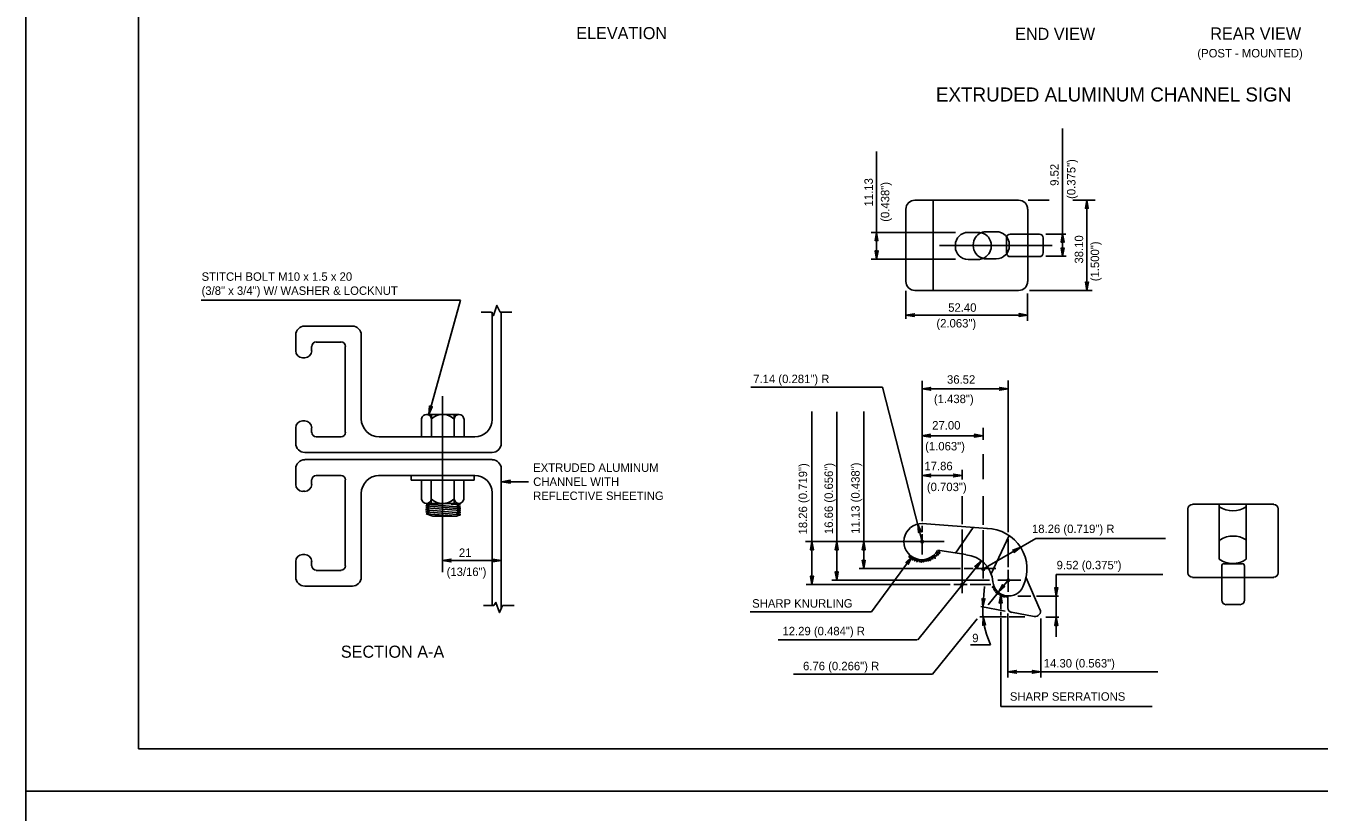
# Model space of a CAD drawing. Extents: x 647822 to 648727, y 298458 to 299646.
# Drawn here: x 647822.3 to 648281.8, y 299044.1 to 299323.4 of the extents above; entities that cross this region are included whole.
import ezdxf

# ---------------------------------------------------------------- set-up
doc = ezdxf.new("R2010")
doc.units = 0
for name, color, linetype in [('1', 7, 'Continuous'), ('2', 7, 'Continuous'), ('3', 7, 'Continuous'), ('XCS-GRID-MIN', 7, 'Continuous')]:
    doc.layers.add(name, color=color, linetype=linetype)

# ---------------------------------------------------------------- blocks, each defined once
blk = doc.blocks.new('RARROW')
at = {"layer": '3'}
blk.add_lwpolyline([(-2.2695, 0.285), (-2.184875, 0.12075), (0, 0), (-2.2695, 0.285), (-2.38575, 0.384625), (0, 0), (-2.183125, -0.108), (-2.262875, -0.2705), (0, 0), (-2.38575, -0.379125), (-2.262875, -0.2705)], dxfattribs=at)

msp = doc.modelspace()

# ---------------------------------------------------------------- linework, layer by layer
at = {"layer": '1'}
for p, q in [((647862.31, 299630.63), (647862.31, 299066.63)), ((648648.31, 299066.63), (647862.31, 299066.63)), ((647862.31, 299066.63), (648448.31, 299066.63))]:
    msp.add_line(p, q, dxfattribs=at)
at = {"layer": '2'}
for p, q in [((648190.69, 299286.92), (648190.69, 299249.57)), ((648124.58, 299278.82), (648124.58, 299250.07)), ((648134.94, 299258.32), (648134.94, 299232.7)), ((648138.19, 299261.57), (648175.06, 299261.57)), ((648144.69, 299261.57), (648144.69, 299229.45)), ((648178.31, 299258.32), (648178.31, 299232.57)), ((648178.44, 299261.57), (648185.95, 299261.57)), ((648194.36, 299261.57), (648202.19, 299261.57)), ((648199.31, 299261.57), (648199.31, 299229.45)), ((648122.7, 299250.07), (648152.6, 299250.07)), ((648124.58, 299250.07), (648124.58, 299240.57)), ((648160.69, 299250.07), (648157.06, 299250.07)), ((648163.25, 299250.31), (648167.12, 299250.31)), ((648178.31, 299249.45), (648172.06, 299249.45)), ((648178.31, 299249.45), (648182.46, 299249.45)), ((648184.69, 299249.45), (648191.81, 299249.45)), ((648190.69, 299249.57), (648190.69, 299241.57)), ((648146.94, 299245.45), (648187.02, 299245.45)), ((648152.56, 299245.57), (648152.56, 299244.95)), ((648158.94, 299245.32), (648158.94, 299245.7)), ((648165.31, 299245.07), (648165.31, 299245.45)), ((648170.71, 299248.1), (648170.71, 299242.8)), ((648171.74, 299245.69), (648171.74, 299245.31)), ((648183.81, 299248.1), (648183.81, 299242.8)), ((648122.7, 299240.57), (648152.6, 299240.57)), ((648124.58, 299240.7), (648124.58, 299240.57)), ((648157.06, 299240.45), (648160.69, 299240.45)), ((648163.06, 299240.7), (648167.06, 299240.7)), ((648172.06, 299241.45), (648178.31, 299241.45)), ((648178.31, 299241.45), (648182.46, 299241.45)), ((648184.69, 299241.57), (648191.94, 299241.57)), ((648190.69, 299241.7), (648190.69, 299241.57)), ((647884.59, 299226), (647976.69, 299226)), ((647965.44, 299185.38), (647976.69, 299226)), ((648134.94, 299229.32), (648134.94, 299219.32)), ((648138.19, 299229.45), (648175.06, 299229.45)), ((648178.19, 299228.32), (648178.19, 299218.7)), ((648178.94, 299229.45), (648201.19, 299229.45)), ((647984.06, 299221.75), (647987.81, 299221.75)), ((647987.94, 299221.75), (647987.94, 299183.63)), ((647990.81, 299221.75), (647994.94, 299221.75)), ((647991.19, 299221.75), (647991.19, 299175.13)), ((648134.94, 299220.7), (648178.19, 299220.7)), ((647918.19, 299208), (647918.19, 299213.5)), ((647921.44, 299216.75), (647938.31, 299216.75)), ((647941.44, 299213.5), (647941.44, 299183.88)), ((647923.81, 299208), (647923.81, 299209.5)), ((647925.44, 299211.13), (647934.31, 299211.13)), ((647935.81, 299209.5), (647935.81, 299179)), ((647920.69, 299205.5), (647921.44, 299205.5)), ((648079.9, 299195.06), (648126.67, 299195.06)), ((648140.81, 299140.13), (648126.67, 299195.06)), ((648140.81, 299147.5), (648140.81, 299197.38)), ((648140.81, 299194.48), (648171.31, 299194.48)), ((648171.31, 299143.63), (648171.31, 299197.5)), ((647970.31, 299129.38), (647970.31, 299191.88)), ((647964.69, 299185.38), (647976.19, 299185.38)), ((647965.44, 299185.38), (647965.44, 299185.38)), ((647966.44, 299177.5), (647966.44, 299185.38)), ((647974.44, 299185.38), (647974.44, 299177.38)), ((648101.63, 299186.46), (648101.63, 299125)), ((648110.4, 299126.5), (648110.4, 299186.31)), ((648120, 299130.63), (648120, 299186.46)), ((647918.19, 299175.13), (647918.19, 299180.63)), ((647921.44, 299183.13), (647920.69, 299183.13)), ((647923.81, 299179), (647923.81, 299180.63)), ((647962.94, 299177.38), (647962.94, 299183.88)), ((647978.06, 299183.88), (647978.06, 299177.38)), ((648162.44, 299176.4), (648162.44, 299180.6)), ((647934.31, 299177.5), (647925.44, 299177.5)), ((647981.81, 299177.5), (647947.94, 299177.5)), ((648140.69, 299177.85), (648162.31, 299177.85)), ((647987.94, 299171.88), (647921.44, 299171.88)), ((648162.44, 299162.4), (648162.44, 299171.27)), ((647987.94, 299169.38), (647921.44, 299169.38)), ((647991.19, 299116.38), (647991.19, 299166.25)), ((647918.19, 299166.13), (647918.19, 299160.5)), ((647923.81, 299162.13), (647923.81, 299160.5)), ((647934.31, 299163.75), (647925.44, 299163.75)), ((647935.81, 299131.63), (647935.81, 299162.13)), ((647981.81, 299163.75), (647947.56, 299163.75)), ((647959.19, 299163.63), (647959.19, 299162)), ((647959.19, 299162), (647981.56, 299162)), ((647962.94, 299161.75), (647962.94, 299155.25)), ((647966.31, 299162), (647966.31, 299153.75)), ((647974.44, 299153.75), (647974.44, 299161.75)), ((647977.94, 299155.25), (647977.94, 299161.75)), ((647981.56, 299162), (647981.56, 299163.63)), ((648140.81, 299163.72), (648154.94, 299163.72)), ((648154.94, 299162.25), (648154.94, 299165.67)), ((647921.44, 299158.13), (647920.69, 299158.13)), ((647941.44, 299127.63), (647941.44, 299157.25)), ((647987.94, 299117.5), (647987.94, 299157.63)), ((647991.44, 299161.5), (648000.94, 299161.5)), ((647991.44, 299161.5), (647991.44, 299161.5)), ((647965.69, 299153.25), (647964.44, 299152.88)), ((647964.44, 299152.88), (647965.56, 299152.5)), ((647965.56, 299152.5), (647964.44, 299152.25)), ((647964.56, 299153.5), (647965.69, 299153.25)), ((647976.69, 299151.88), (647964.56, 299152.88)), ((647964.69, 299153.75), (647976.06, 299153.75)), ((647976.69, 299152.5), (647964.81, 299153.5)), ((647976.69, 299153.25), (647973.44, 299153.5)), ((648154.94, 299146.38), (648154.94, 299156.34)), ((648162.44, 299146.13), (648162.44, 299156.34)), ((648265.69, 299153.5), (648236.81, 299153.5)), ((648246.31, 299153.38), (648246.31, 299133.94)), ((648255.94, 299153.38), (648255.94, 299133.99)), ((647965.56, 299151.75), (647964.31, 299151.5)), ((647964.31, 299151.5), (647965.69, 299151.13)), ((647964.44, 299152.25), (647965.56, 299151.75)), ((647976.56, 299150.5), (647964.44, 299151.5)), ((647965.69, 299151.13), (647964.44, 299150.75)), ((647964.44, 299150.75), (647965.56, 299150.38)), ((647976.69, 299151.25), (647964.56, 299152.25)), ((647976.69, 299149.75), (647964.56, 299150.75)), ((647965.56, 299150.38), (647964.56, 299150.13)), ((647964.56, 299150.13), (647966.94, 299149.25)), ((647975.19, 299149.25), (647964.69, 299150.13)), ((647975.56, 299149.25), (647966.94, 299149.25)), ((648235.19, 299151.88), (648235.19, 299129.13)), ((648267.31, 299151.88), (648267.31, 299129.13)), ((648140.81, 299146.63), (648163.94, 299144.88)), ((648140.81, 299143.63), (648140.81, 299145.88)), ((648152.56, 299136.13), (648158.94, 299145.25)), ((648154.94, 299121.88), (648154.94, 299144.5)), ((648162.44, 299127.13), (648162.44, 299144.25)), ((648099.38, 299140.25), (648148.56, 299140.25)), ((648140.81, 299135.63), (648140.81, 299142.88)), ((648162.31, 299130.38), (648181.19, 299141.38)), ((648165.31, 299128.75), (648171.69, 299142.38)), ((648171.31, 299131.13), (648171.31, 299141.13)), ((648181.19, 299141.38), (648227.24, 299141.38)), ((647920.69, 299135.63), (647921.44, 299135.63)), ((648122.72, 299115.26), (648137.19, 299134.88)), ((648156.31, 299135.63), (648146.31, 299137.13)), ((647918.19, 299133.25), (647918.19, 299127.63)), ((647923.81, 299133.25), (647923.81, 299131.63)), ((647925.44, 299130), (647934.31, 299130)), ((647970.31, 299133.5), (647991.19, 299133.5)), ((648118.41, 299130.63), (648154.44, 299130.63)), ((648139.23, 299105.38), (648161.81, 299133.38)), ((648155.69, 299130.63), (648158.94, 299130.63)), ((648159.81, 299130.63), (648166.94, 299130.63)), ((648162.44, 299130.63), (648162.44, 299130.63)), ((648171.31, 299122.38), (648171.31, 299130.25)), ((648247.19, 299119.38), (648247.19, 299131.63)), ((648248.06, 299132.38), (648254.44, 299132.38)), ((648255.31, 299131.63), (648255.31, 299119.38)), ((648099.53, 299125), (648150.69, 299125)), ((648108.67, 299126.5), (648164.69, 299126.5)), ((648152.06, 299125), (648156.81, 299125)), ((648154.94, 299125), (648154.94, 299125)), ((648154.94, 299125), (648154.94, 299125)), ((648157.81, 299125), (648165.19, 299125)), ((648164.23, 299117.72), (648171.31, 299126.5)), ((648167.69, 299126.5), (648175.81, 299126.5)), ((648171.31, 299126.5), (648171.31, 299126.5)), ((648182.56, 299116.13), (648177.69, 299127.38)), ((648188.44, 299120.88), (648188.44, 299128.5)), ((648188.44, 299128.5), (648226.24, 299128.5)), ((648265.69, 299127.5), (648236.81, 299127.5)), ((647921.44, 299124.38), (647938.31, 299124.38)), ((648162.36, 299116.98), (648162.94, 299124.25)), ((648168.69, 299116.25), (648168.69, 299121.38)), ((648171.19, 299120.88), (648171.19, 299116.63)), ((648174.81, 299120.88), (648179.44, 299120.88)), ((648181.44, 299120.88), (648189.19, 299120.88)), ((648188.44, 299113.25), (648188.44, 299120.88)), ((647984.94, 299117.5), (647988.56, 299117.5)), ((647991.69, 299117.5), (647995.81, 299117.5)), ((648161.56, 299117.13), (648170.31, 299115.5)), ((648248.81, 299117.88), (648253.69, 299117.88)), ((648079.62, 299115.26), (648122.72, 299115.26)), ((648144.43, 299093.18), (648160.26, 299112.8)), ((648161.31, 299113.5), (648170.69, 299113.5)), ((648168.69, 299114), (648168.69, 299115.25)), ((648168.69, 299081.7), (648168.69, 299113)), ((648171.19, 299091.98), (648171.19, 299114.63)), ((648171.69, 299113.5), (648177.31, 299113.5)), ((648172.56, 299115.13), (648180.56, 299113.63)), ((648182.94, 299091.98), (648182.94, 299112.88)), ((648184.69, 299113.38), (648189.31, 299113.38)), ((648188.44, 299106.38), (648188.44, 299113.5)), ((648089.59, 299105.38), (648138.98, 299105.38)), ((648157.97, 299103.56), (648165.1, 299103.56)), ((648095.04, 299093.18), (648144.43, 299093.18)), ((648171.19, 299093.98), (648224.49, 299093.98)), ((648168.69, 299081.7), (648222.48, 299081.7))]:
    msp.add_line(p, q, dxfattribs=at)
for points in [[(647987.81, 299221.75), (647988.44, 299220.5), (647989.69, 299224.13), (647990.81, 299221.75)], [(647975.94, 299153.5), (647976.56, 299153.25), (647975.56, 299152.88), (647976.69, 299152.5), (647975.56, 299152.25), (647976.69, 299151.88), (647975.56, 299151.5), (647976.69, 299151.13), (647975.56, 299150.75), (647976.69, 299150.5), (647975.44, 299150.13), (647976.69, 299149.75), (647975.19, 299149.25)], [(647988.56, 299117.5), (647989.31, 299118.63), (647990.56, 299115), (647991.69, 299117.5)]]:
    msp.add_lwpolyline(points, dxfattribs=at)
for centre in [(648140.78, 299140.23), (648162.53, 299130.44), (648154.89, 299124.97), (648171.35, 299126.49)]:
    msp.add_circle(centre, 0.443, dxfattribs=at)
for centre, radius, start, end in [((648138.18, 299258.32), 3.2, 90, 180), ((648175.05, 299258.32), 3.2, 0, 90), ((648157.06, 299245.57), 4.5, 90, 180), ((648163.56, 299245.69), 4.62, 112.9887, 180), ((648160.83, 299245.48), 4.59, 77.9667, 91.7716), ((648163.56, 299245.69), 4.62, 90, 112.8645), ((648160.68, 299245.49), 4.62, 0, 75.8124), ((648167.12, 299245.69), 4.62, 0, 90), ((648172.06, 299248.1), 1.35, 90, 180), ((648182.46, 299248.1), 1.35, 0, 90), ((648157.06, 299244.95), 4.5, 180, 270), ((648163.56, 299245.31), 4.62, 180, 253.8798), ((648160.68, 299245.1), 4.62, 290.5941, 0), ((648167.12, 299245.31), 4.62, 270, 0), ((648160.48, 299245.54), 5.1, 272.3653, 291.0122), ((648163.56, 299245.31), 4.62, 254.1406, 270), ((648172.06, 299242.8), 1.35, 180, 270), ((648182.46, 299242.8), 1.35, 270, 0), ((648138.18, 299232.66), 3.2, 180, 270), ((648175.05, 299232.66), 3.2, 270, 0), ((647921.4, 299213.57), 3.2, 90, 180), ((647938.29, 299213.57), 3.2, 0, 90), ((647920.66, 299208), 2.46, 180, 270), ((647921.4, 299208), 2.46, 270, 0), ((647925.47, 299209.55), 1.6, 90, 180), ((647934.27, 299209.55), 1.6, 0, 90), ((647920.66, 299180.65), 2.46, 90, 180), ((647921.4, 299180.65), 2.46, 0, 90), ((647947.89, 299183.87), 6.4, 180, 270), ((647981.81, 299183.63), 6.16, 270, 0), ((647925.47, 299179.07), 1.6, 180, 270), ((647934.27, 299179.07), 1.6, 270, 0), ((647921.4, 299175.08), 3.2, 180, 270), ((647988, 299175.08), 3.2, 270, 0), ((647921.4, 299166.11), 3.2, 90, 180), ((647988, 299166.11), 3.2, 0, 90), ((647925.47, 299162.12), 1.6, 90, 180), ((647934.27, 299162.12), 1.6, 0, 90), ((647947.89, 299157.32), 6.4, 90, 180), ((647981.81, 299157.57), 6.16, 0, 90), ((647920.66, 299160.54), 2.46, 180, 270), ((647921.4, 299160.54), 2.46, 270, 0), ((648236.8, 299151.84), 1.6, 90, 180), ((648251.14, 299159.57), 8.44, 235.4439, 305.1656), ((648265.66, 299151.84), 1.6, 0, 90), ((648140.68, 299140.21), 6.4, 88.6252, 330.6548), ((648163.58, 299130.46), 14.44, 334.348, 89.3872), ((648246.83, 299140.51), 0.4, 123.07, 180), ((648251.22, 299133.77), 8.44, 56.7397, 123.07), ((647920.66, 299133.2), 2.46, 90, 180), ((647921.4, 299133.2), 2.46, 0, 90), ((648155.5, 299125.15), 10.43, 4.0856, 85.4934), ((647925.47, 299131.65), 1.6, 180, 270), ((647934.27, 299131.65), 1.6, 270, 0), ((648251.09, 299140.9), 8.44, 235.5078, 305.0689), ((648248.03, 299131.59), 0.8, 90, 180), ((648254.46, 299131.59), 0.8, 0, 90), ((647921.4, 299127.63), 3.2, 180, 270), ((647938.29, 299127.63), 3.2, 270, 0), ((648171.48, 299126.51), 5.6, 185.7365, 335.7963), ((648236.8, 299129.14), 1.6, 180, 270), ((648265.66, 299129.14), 1.6, 270, 0), ((648187.85, 299115.48), 25.53, 176.3698, 184.437), ((648172.83, 299116.67), 1.6, 180, 259.2899), ((648180.94, 299115.42), 1.85, 259.5085, 24.0163), ((648248.83, 299119.42), 1.6, 180, 270), ((648253.66, 299119.42), 1.6, 270, 0), ((648191.91, 299116.21), 29.64, 184.2804, 205.2635)]:
    msp.add_arc(centre, radius, start, end, dxfattribs=at)
for centre, major_axis, ratio, start_param, end_param in [((647964.69, 299183.34), (0, 2.07), 0.888639, 4.973303, 7.593068), ((647970.43, 299178.2), (0, 7.22), 0.88864, 5.618065, 6.948305), ((647976.24, 299183.41), (0, 2.01), 0.888639, 4.948347, 7.618023), ((647964.63, 299155.85), (0, -2.07), 0.88864, 4.973303, 7.593068), ((647970.38, 299161), (0, -7.22), 0.88864, 5.618065, 6.948305), ((647976.19, 299155.79), (0, -2.01), 0.888639, 4.948347, 7.618023)]:
    msp.add_ellipse(centre, major_axis=major_axis, ratio=ratio, start_param=start_param, end_param=end_param, dxfattribs=at)
for points in [[(648136.31, 299135.38), (648136.19, 299134.63), (648136.94, 299135), (648136.81, 299134.13), (648137.44, 299134.38), (648137.31, 299133.75), (648138.06, 299134.13), (648138.06, 299133.38), (648138.69, 299133.75), (648138.94, 299133), (648139.44, 299133.75), (648139.94, 299133), (648140.31, 299133.38), (648140.56, 299132.88), (648140.94, 299133.63), (648141.31, 299133), (648141.69, 299133.88), (648142.06, 299133.13)], [(648141.94, 299133.88), (648142.31, 299133.25), (648142.69, 299134), (648143.06, 299133.38), (648143.44, 299134.13), (648143.69, 299133.5), (648144.06, 299134.38), (648144.56, 299134), (648144.69, 299134.75), (648145.44, 299134.25), (648145.19, 299135.13), (648145.94, 299135.13), (648145.94, 299135.75), (648146.56, 299135.5), (648146.19, 299136.25), (648147.06, 299136.13), (648146.56, 299137), (648147.19, 299136.88)], [(648166.19, 299124.63), (648165.81, 299123.88), (648166.56, 299123.88), (648166.19, 299123.25), (648166.94, 299123.25), (648166.44, 299122.75), (648167.31, 299122.75), (648166.94, 299122.13), (648167.81, 299122.25), (648167.69, 299121.5), (648168.44, 299121.75), (648168.44, 299121), (648169.06, 299121.38), (648169.06, 299120.63), (648169.81, 299121.13), (648169.81, 299120.5), (648170.56, 299121), (648170.56, 299120.38)]]:
    msp.add_spline(points, degree=3, dxfattribs=at)
at = {"layer": 'XCS-GRID-MIN'}
for points in [[(647822.31, 299645.63), (648663.31, 299645.63), (648663.31, 299051.63), (647822.31, 299051.63)], [(647822.31, 299051.63), (648663.31, 299051.63), (648663.31, 298457.63), (647822.31, 298457.63)]]:
    msp.add_lwpolyline(points, close=True, dxfattribs=at)

# ---------------------------------------------------------------- block references
at = {"layer": '2'}
for p, xscale, yscale, rotation in [((648199.31, 299261.57), 1.2574347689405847, 1.3092961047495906, 89.99999999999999), ((648124.58, 299250.07), 1.2574347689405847, 1.3092961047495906, 89.99999999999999), ((648190.69, 299249.57), 1.2574347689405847, 1.3092961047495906, 89.99999999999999), ((648190.69, 299241.57), 1.2574347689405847, 1.3092961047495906, -90.00000000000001), ((648124.58, 299240.57), 1.2574347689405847, 1.3092961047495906, -90.00000000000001), ((648199.31, 299229.45), 1.2574347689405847, 1.3092961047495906, -90.00000000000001), ((648134.94, 299220.7), 1.2574347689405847, 1.3092961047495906, 180), ((648140.81, 299194.48), 1.2574347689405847, 1.3092961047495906, 180), ((647965.44, 299185.38), 1.257434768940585, 1.3092961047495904, -105.47863816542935), ((648140.69, 299177.85), 1.2574347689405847, 1.3092961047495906, 180), ((647991.44, 299161.5), 1.2574347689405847, 1.3092961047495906, 180), ((648140.81, 299163.72), 1.2574347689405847, 1.3092961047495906, 180), ((648139.19, 299146.43), 1.2574347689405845, 1.3092961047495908, 104.99324708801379), ((648101.63, 299140.25), 1.2574347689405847, 1.3092961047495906, 89.99999999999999), ((648110.4, 299140.25), 1.2574347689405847, 1.3092961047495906, 89.99999999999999), ((648120, 299140.25), 1.2574347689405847, 1.3092961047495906, 89.99999999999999), ((648175.81, 299138.25), 1.257434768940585, 1.3092961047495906, 28.994801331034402), ((648137.19, 299134.88), 1.2574347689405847, 1.3092961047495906, 54.05716951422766), ((647970.31, 299133.5), 1.2574347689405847, 1.3092961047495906, 180), ((648110.4, 299126.5), 1.2574347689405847, 1.3092961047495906, -90.00000000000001), ((648120, 299130.63), 1.2574347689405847, 1.3092961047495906, -90.00000000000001), ((648161.81, 299133.38), 1.2574347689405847, 1.3092961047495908, 49.686306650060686), ((648101.63, 299125), 1.2574347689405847, 1.3092961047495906, -90.00000000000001), ((648167.87, 299122.23), 1.257434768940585, 1.3092961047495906, -128.70988085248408), ((648168.69, 299121.38), 1.2574347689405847, 1.3092961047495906, 89.99999999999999), ((648188.44, 299120.88), 1.2574347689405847, 1.3092961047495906, -90.00000000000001), ((648162.37, 299116.97), 1.257434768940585, 1.3092961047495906, -93.60514013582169), ((648162.39, 299113.5), 1.2574347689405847, 1.3092961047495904, 97.67734975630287), ((648188.44, 299113.38), 1.2574347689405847, 1.3092961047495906, 89.99999999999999), ((648171.19, 299093.98), 1.2574347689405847, 1.3092961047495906, 180)]:
    msp.add_blockref('RARROW', p, dxfattribs=dict(at, xscale=xscale, yscale=yscale, rotation=rotation))
at = {"layer": '2', "xscale": 1.2574347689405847, "yscale": 1.3092961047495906}
for p in [(648178.19, 299220.7), (648171.31, 299194.48), (648162.31, 299177.85), (648154.94, 299163.72), (647991.19, 299133.5), (648182.94, 299093.98)]:
    msp.add_blockref('RARROW', p, dxfattribs=at)

# ---------------------------------------------------------------- texts
at = {"layer": '2'}
for s, height, p in [('ELEVATION', 4.3, (648017.87, 299318.71)), ('END VIEW', 4.3, (648173.8, 299318.44)), ('REAR VIEW', 4.3, (648243.15, 299318.57)), ('(POST - MOUNTED)', 3, (648238.55, 299312.22)), ('EXTRUDED ALUMINUM CHANNEL SIGN', 5, (648145.65, 299296.56)), ('STITCH BOLT M10 x 1.5 x 20 ', 3, (647884.74, 299232.87)), ('(3/8" x 3/4") W/ WASHER & LOCKNUT', 3, (647884.74, 299227.87)), ('52.40', 3, (648150.02, 299221.87)), ('(2.063")', 3, (648145.83, 299216.29)), ('7.14 (0.281") R', 3, (648080.75, 299196.53)), ('36.52', 3, (648149.6, 299196.32)), ('(1.438")', 3, (648144.94, 299189.42)), ('27.00', 3, (648144.34, 299180.04)), ('(1.063")', 3, (648141.83, 299172.62)), ('EXTRUDED ALUMINUM', 3, (648002.56, 299165)), ('17.86', 3, (648141.57, 299165.57)), ('CHANNEL WITH', 3, (648002.56, 299160)), ('REFLECTIVE SHEETING', 3, (648002.56, 299155)), ('(0.703")', 3, (648142.45, 299158.16)), ('18.26 (0.719") R', 3, (648179.79, 299143.26)), (' 21', 3, (647975.05, 299134.78)), ('(13/16")', 3, (647971.8, 299128)), ('9.52 (0.375")', 3, (648188.54, 299130.39)), ('SHARP KNURLING', 3, (648080.37, 299116.77)), ('12.29 (0.484") R', 3, (648091.14, 299106.95)), ('9', 3, (648158.56, 299104.49)), ('SECTION A-A', 4.3, (647934.23, 299098.97)), ('6.76 (0.266") R', 3, (648098.45, 299094.53)), ('14.30 (0.563")', 3, (648183.97, 299095.51)), ('SHARP SERRATIONS', 3, (648171.93, 299083.7))]:
    msp.add_text(s, height=height, dxfattribs=at).set_placement(p)
for s, p in [('9.52', (648189.29, 299266.61)), (' (0.375") ', (648195.24, 299260.84)), ('11.13 ', (648123.25, 299259.3)), (' (0.438") ', (648129.1, 299252.73)), ('38.10', (648197.97, 299238.99)), (' (1.500") ', (648203.65, 299231.6)), ('18.26 (0.719")', (648099.9, 299142.77)), ('16.66 (0.656")', (648109.08, 299142.9)), ('11.13 (0.438")', (648118.57, 299143.02))]:
    msp.add_text(s, height=3, rotation=90, dxfattribs=at).set_placement(p)

doc.saveas('drawing.dxf')
